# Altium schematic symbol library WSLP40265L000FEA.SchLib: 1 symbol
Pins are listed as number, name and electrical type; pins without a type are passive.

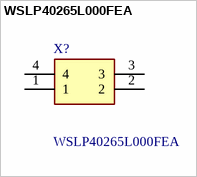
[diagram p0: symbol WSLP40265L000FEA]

## WSLP40265L000FEA
designator X?
5 mOhms +/-1% 5W Chip Resistor Nonstandard Anti-Sulfur, Automotive AEC-Q200, Current Sense, Pulse Withstanding Metal Element, -65C ~ 170C; Manufacturer_Name: Vishay; Geometry.Height: 2.99mm
footprint WSLP40265L000FEA
pins: 1, 2, 3, 4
